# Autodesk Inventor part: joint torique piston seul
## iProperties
Author: User
Created: 2002-03
Part Number: joint torique piston seul
Material: Par défaut
Document SubType Name: Modélisation
Designer: User
Control State: 0
Master: False
Checked Out: False
PropertySet Name: Design Tracking Control
Shininess: 20.0
Length Units: 11269
Angle Units: 11283
Time Units: 11279
Mass Units: 11290
Length Display Precision: 3
Angle Display Precision: 2
Compacted: False
PropertySet Name: _Private Model Information
Density: 0.0
Volumn: 0.0
Area: 0.0
PropertySet Name: Model Information
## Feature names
1. Révolution1 [Revolution]
